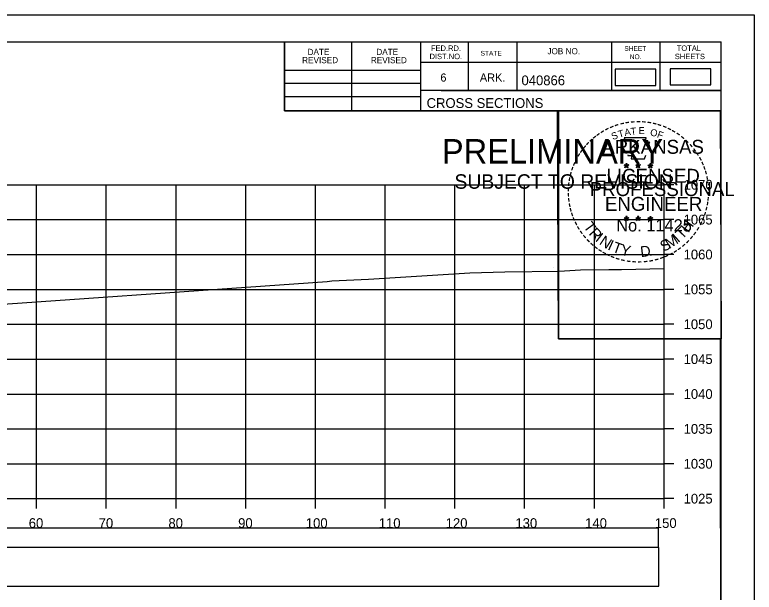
# Model space of a CAD drawing. Extents: x 1370565 to 1374448, y 301010 to 304637.
# Drawn here: x 1370791.9 to 1370898, y 303701.1 to 303783.9 of the extents above; entities that cross this region are included whole.
import ezdxf

# ---------------------------------------------------------------- set-up
doc = ezdxf.new("R2010")
doc.units = 0
for name, color, linetype in [('Default', 7, 'Continuous'), ('R_Axis', 7, 'Continuous'), ('R_Axis Annot', 7, 'Continuous'), ('R_Border', 7, 'Continuous'), ('R_Border PE', 7, 'Continuous'), ('R_Border Prem', 7, 'Continuous'), ('R_Drive', 7, 'Continuous'), ('R_Exist Surface', 7, 'Continuous'), ('R_Grid', 7, 'Continuous'), ('R_No Plot', 7, 'Continuous')]:
    doc.layers.add(name, color=color, linetype=linetype)

msp = doc.modelspace()

# ---------------------------------------------------------------- linework, layer by layer
at = {"layer": 'Default'}
msp.add_lwpolyline([(1370878.02, 303773.77), (1370883.85, 303773.77), (1370883.85, 303776.08), (1370878.02, 303776.08)], close=True, dxfattribs=at)
at = {"layer": 'R_Axis'}
for p, q in [((1370885.03, 303714.53), (1370885.03, 303759.53)), ((1370886.43, 303759.53), (1370885.03, 303759.53)), ((1370886.43, 303754.53), (1370885.03, 303754.53)), ((1370886.43, 303749.53), (1370885.03, 303749.53)), ((1370886.43, 303744.53), (1370885.03, 303744.53)), ((1370886.43, 303739.53), (1370885.03, 303739.53)), ((1370886.43, 303734.53), (1370885.03, 303734.53)), ((1370886.43, 303729.53), (1370885.03, 303729.53)), ((1370886.43, 303724.53), (1370885.03, 303724.53)), ((1370886.43, 303719.53), (1370885.03, 303719.53)), ((1370585.03, 303714.53), (1370885.03, 303714.53)), ((1370795.03, 303713.13), (1370795.03, 303714.53)), ((1370805.03, 303713.13), (1370805.03, 303714.53)), ((1370815.03, 303713.13), (1370815.03, 303714.53)), ((1370825.03, 303713.13), (1370825.03, 303714.53)), ((1370835.03, 303713.13), (1370835.03, 303714.53)), ((1370845.03, 303713.13), (1370845.03, 303714.53)), ((1370855.03, 303713.13), (1370855.03, 303714.53)), ((1370865.03, 303713.13), (1370865.03, 303714.53)), ((1370875.03, 303713.13), (1370875.03, 303714.53)), ((1370885.03, 303713.13), (1370885.03, 303714.53)), ((1370886.43, 303714.53), (1370885.03, 303714.53))]:
    msp.add_line(p, q, dxfattribs=at)
at = {"layer": 'R_Border'}
for p, q in [((1370577.03, 303779.99), (1370893.21, 303779.99)), ((1370830.57, 303770.11), (1370830.57, 303779.99)), ((1370840.25, 303770.11), (1370840.25, 303779.99)), ((1370850.11, 303779.99), (1370850.11, 303770.11)), ((1370856.95, 303779.99), (1370856.95, 303773.05)), ((1370863.89, 303779.99), (1370863.89, 303773.05)), ((1370877.47, 303779.99), (1370877.47, 303773.05)), ((1370884.41, 303779.99), (1370884.41, 303773.05)), ((1370893.21, 303574.53), (1370893.21, 303779.99)), ((1370893.21, 303777.05), (1370850.11, 303777.05)), ((1370893.21, 303777.07), (1370893.21, 303777.07)), ((1370830.57, 303775.97), (1370850.11, 303775.97)), ((1370830.57, 303774.11), (1370850.11, 303774.11)), ((1370893.21, 303773.05), (1370850.11, 303773.05)), ((1370853.07, 303773.05), (1370893.21, 303773.05)), ((1370830.57, 303772.17), (1370850.11, 303772.17)), ((1370893.21, 303770.11), (1370830.57, 303770.11))]:
    msp.add_line(p, q, dxfattribs=at)
at = {"layer": 'R_Border PE'}
for p, q in [((1370879.29, 303762.37), (1370879.64, 303762.26)), ((1370879.29, 303762.37), (1370879.54, 303762.32)), ((1370879.29, 303762.37), (1370879.53, 303762.24)), ((1370879.64, 303762.62), (1370879.6, 303762.37)), ((1370879.64, 303762.26), (1370879.64, 303762.62)), ((1370879.64, 303762.62), (1370879.69, 303762.37)), ((1370879.99, 303762.37), (1370879.64, 303762.26)), ((1370879.99, 303762.37), (1370879.7, 303762.32)), ((1370879.99, 303762.37), (1370879.78, 303762.26)), ((1370880.96, 303762.37), (1370881.31, 303762.26)), ((1370880.96, 303762.37), (1370881.21, 303762.32)), ((1370880.96, 303762.37), (1370881.2, 303762.24)), ((1370881.31, 303762.62), (1370881.27, 303762.37)), ((1370881.31, 303762.26), (1370881.31, 303762.62)), ((1370881.31, 303762.62), (1370881.36, 303762.37)), ((1370881.66, 303762.37), (1370881.31, 303762.26)), ((1370881.66, 303762.37), (1370881.37, 303762.32)), ((1370881.66, 303762.37), (1370881.45, 303762.26)), ((1370882.72, 303762.35), (1370883.07, 303762.24)), ((1370882.72, 303762.35), (1370882.98, 303762.31)), ((1370882.72, 303762.35), (1370882.96, 303762.23)), ((1370883.07, 303762.61), (1370883.03, 303762.36)), ((1370883.07, 303762.24), (1370883.07, 303762.61)), ((1370883.07, 303762.61), (1370883.12, 303762.36)), ((1370883.42, 303762.35), (1370883.07, 303762.24)), ((1370883.42, 303762.35), (1370883.13, 303762.31)), ((1370883.42, 303762.35), (1370883.22, 303762.25)), ((1370879.42, 303761.96), (1370879.64, 303762.26)), ((1370879.42, 303761.96), (1370879.55, 303762.2)), ((1370879.42, 303761.96), (1370879.64, 303762.18)), ((1370879.85, 303761.96), (1370879.64, 303762.26)), ((1370879.85, 303761.96), (1370879.64, 303762.17)), ((1370879.85, 303761.96), (1370879.72, 303762.25)), ((1370881.09, 303761.96), (1370881.31, 303762.26)), ((1370881.09, 303761.96), (1370881.22, 303762.2)), ((1370881.09, 303761.96), (1370881.31, 303762.18)), ((1370881.52, 303761.96), (1370881.31, 303762.26)), ((1370881.52, 303761.96), (1370881.31, 303762.17)), ((1370881.52, 303761.96), (1370881.39, 303762.25)), ((1370882.86, 303761.95), (1370883.07, 303762.24)), ((1370882.86, 303761.95), (1370882.98, 303762.19)), ((1370882.86, 303761.95), (1370883.07, 303762.16)), ((1370883.29, 303761.95), (1370883.07, 303762.24)), ((1370883.29, 303761.95), (1370883.07, 303762.16)), ((1370883.29, 303761.95), (1370883.15, 303762.24)), ((1370879.64, 303755.05), (1370879.59, 303754.8)), ((1370879.64, 303754.68), (1370879.64, 303755.05)), ((1370879.64, 303755.05), (1370879.68, 303754.8)), ((1370881.3, 303755.05), (1370881.26, 303754.8)), ((1370881.3, 303754.68), (1370881.3, 303755.05)), ((1370881.3, 303755.05), (1370881.35, 303754.8)), ((1370883.07, 303755.04), (1370883.03, 303754.79)), ((1370883.07, 303754.67), (1370883.07, 303755.04)), ((1370883.07, 303755.04), (1370883.12, 303754.79)), ((1370879.29, 303754.79), (1370879.64, 303754.68)), ((1370879.29, 303754.79), (1370879.54, 303754.75)), ((1370879.29, 303754.79), (1370879.52, 303754.67)), ((1370879.42, 303754.39), (1370879.64, 303754.68)), ((1370879.42, 303754.39), (1370879.55, 303754.63)), ((1370879.42, 303754.39), (1370879.63, 303754.6)), ((1370879.85, 303754.39), (1370879.63, 303754.6)), ((1370879.98, 303754.79), (1370879.64, 303754.68)), ((1370879.85, 303754.39), (1370879.64, 303754.68)), ((1370879.98, 303754.79), (1370879.7, 303754.74)), ((1370879.85, 303754.39), (1370879.71, 303754.68)), ((1370879.98, 303754.79), (1370879.78, 303754.69)), ((1370880.96, 303754.79), (1370881.3, 303754.68)), ((1370880.96, 303754.79), (1370881.21, 303754.75)), ((1370880.96, 303754.79), (1370881.19, 303754.67)), ((1370881.09, 303754.39), (1370881.3, 303754.68)), ((1370881.09, 303754.39), (1370881.21, 303754.63)), ((1370881.09, 303754.39), (1370881.3, 303754.6)), ((1370881.65, 303754.79), (1370881.3, 303754.68)), ((1370881.52, 303754.39), (1370881.3, 303754.68)), ((1370881.52, 303754.39), (1370881.3, 303754.6)), ((1370881.65, 303754.79), (1370881.37, 303754.74)), ((1370881.52, 303754.39), (1370881.38, 303754.68)), ((1370881.65, 303754.79), (1370881.45, 303754.69)), ((1370882.72, 303754.78), (1370883.07, 303754.67)), ((1370882.72, 303754.78), (1370882.98, 303754.74)), ((1370882.72, 303754.78), (1370882.96, 303754.66)), ((1370882.86, 303754.38), (1370883.07, 303754.67)), ((1370882.86, 303754.38), (1370882.98, 303754.62)), ((1370882.86, 303754.38), (1370883.07, 303754.59)), ((1370883.42, 303754.78), (1370883.07, 303754.67)), ((1370883.28, 303754.38), (1370883.07, 303754.67)), ((1370883.28, 303754.38), (1370883.07, 303754.59)), ((1370883.42, 303754.78), (1370883.13, 303754.73)), ((1370883.28, 303754.38), (1370883.15, 303754.67)), ((1370883.42, 303754.78), (1370883.21, 303754.68))]:
    msp.add_line(p, q, dxfattribs=at)
for points in [[(1370879.33, 303766.24), (1370879.6, 303765.42)], [(1370882.84, 303765.32), (1370882.98, 303765.61), (1370882.3, 303765.58), (1370882.45, 303766.24), (1370879.33, 303766.24)], [(1370879.82, 303763.82), (1370879.82, 303763.73), (1370880.39, 303763.72), (1370880.33, 303763.24), (1370882.2, 303763.24), (1370882.4, 303763.78)], [(1370879.64, 303762.62), (1370879.85, 303761.96), (1370879.29, 303762.37), (1370879.99, 303762.37), (1370879.42, 303761.96), (1370879.64, 303762.62)], [(1370881.31, 303762.62), (1370881.52, 303761.96), (1370880.96, 303762.37), (1370881.66, 303762.37), (1370881.09, 303761.96), (1370881.31, 303762.62)], [(1370883.07, 303762.61), (1370883.29, 303761.95), (1370882.72, 303762.35), (1370883.42, 303762.35), (1370882.86, 303761.95), (1370883.07, 303762.61)], [(1370879.64, 303755.05), (1370879.85, 303754.39), (1370879.29, 303754.79), (1370879.98, 303754.79), (1370879.42, 303754.39), (1370879.64, 303755.05)], [(1370881.3, 303755.05), (1370881.52, 303754.39), (1370880.96, 303754.79), (1370881.65, 303754.79), (1370881.09, 303754.39), (1370881.3, 303755.05)], [(1370883.07, 303755.04), (1370883.28, 303754.38), (1370882.72, 303754.78), (1370883.42, 303754.78), (1370882.86, 303754.38), (1370883.07, 303755.04)]]:
    msp.add_lwpolyline(points, dxfattribs=at)
for centre, radius in [((1370879.64, 303762.26), 0.172), ((1370879.64, 303762.26), 0.145), ((1370879.64, 303762.26), 0.116), ((1370879.64, 303762.26), 0.0991), ((1370879.64, 303762.26), 0.0747), ((1370881.31, 303762.26), 0.172), ((1370881.31, 303762.26), 0.145), ((1370881.31, 303762.26), 0.116), ((1370881.31, 303762.26), 0.0991), ((1370881.31, 303762.26), 0.0747), ((1370883.07, 303762.24), 0.172), ((1370883.07, 303762.24), 0.145), ((1370883.07, 303762.24), 0.116), ((1370883.07, 303762.24), 0.0991), ((1370883.07, 303762.24), 0.0747), ((1370879.64, 303762.26), 0.0495), ((1370879.64, 303762.26), 0.0296), ((1370881.31, 303762.26), 0.0495), ((1370881.31, 303762.26), 0.0296), ((1370883.07, 303762.24), 0.0495), ((1370883.07, 303762.24), 0.0296), ((1370879.63, 303754.68), 0.172), ((1370879.63, 303754.68), 0.145), ((1370879.63, 303754.68), 0.116), ((1370879.63, 303754.68), 0.0991), ((1370879.63, 303754.68), 0.0747), ((1370879.63, 303754.68), 0.0495), ((1370879.63, 303754.68), 0.0296), ((1370881.3, 303754.68), 0.172), ((1370881.3, 303754.68), 0.145), ((1370881.3, 303754.68), 0.116), ((1370881.3, 303754.68), 0.0991), ((1370881.3, 303754.68), 0.0747), ((1370881.3, 303754.68), 0.0495), ((1370881.3, 303754.68), 0.0296), ((1370883.07, 303754.67), 0.172), ((1370883.07, 303754.67), 0.145), ((1370883.07, 303754.67), 0.116), ((1370883.07, 303754.67), 0.0991), ((1370883.07, 303754.67), 0.0747), ((1370883.07, 303754.67), 0.0495), ((1370883.07, 303754.67), 0.0296)]:
    msp.add_circle(centre, radius, dxfattribs=at)
at = {"layer": 'R_Drive'}
for points in [[(1370885.89, 303773.84), (1370891.72, 303773.84), (1370891.72, 303776.15), (1370885.89, 303776.15)], [(1370585.8, 303707.57), (1370884.22, 303707.57), (1370884.22, 303710.28), (1370585.8, 303710.28)], [(1370585.86, 303701.99), (1370884.28, 303701.99), (1370884.28, 303707.52), (1370585.86, 303707.52)]]:
    msp.add_lwpolyline(points, close=True, dxfattribs=at)
at = {"layer": 'R_Exist Surface'}
msp.add_lwpolyline([(1370779.23, 303741.65), (1370836.69, 303745.66), (1370837.37, 303745.75), (1370842.65, 303745.98), (1370857.18, 303746.91), (1370862.19, 303747.02), (1370869.97, 303747.14), (1370873.06, 303747.35), (1370877.11, 303747.4), (1370878.94, 303747.39), (1370885.03, 303747.5)], dxfattribs=at)
at = {"layer": 'R_Grid'}
for p, q in [((1370585.03, 303759.53), (1370885.03, 303759.53)), ((1370795.03, 303714.53), (1370795.03, 303759.53)), ((1370805.03, 303714.53), (1370805.03, 303759.53)), ((1370815.03, 303714.53), (1370815.03, 303759.53)), ((1370825.03, 303714.53), (1370825.03, 303759.53)), ((1370835.03, 303714.53), (1370835.03, 303759.53)), ((1370845.03, 303714.53), (1370845.03, 303759.53)), ((1370855.03, 303714.53), (1370855.03, 303759.53)), ((1370865.03, 303714.53), (1370865.03, 303759.53)), ((1370875.03, 303714.53), (1370875.03, 303759.53)), ((1370885.03, 303714.53), (1370885.03, 303759.53)), ((1370585.03, 303754.53), (1370885.03, 303754.53)), ((1370585.03, 303749.53), (1370885.03, 303749.53)), ((1370585.03, 303744.53), (1370885.03, 303744.53)), ((1370585.03, 303739.53), (1370885.03, 303739.53)), ((1370585.03, 303734.53), (1370885.03, 303734.53)), ((1370585.03, 303729.53), (1370885.03, 303729.53)), ((1370585.03, 303724.53), (1370885.03, 303724.53)), ((1370585.03, 303719.53), (1370885.03, 303719.53)), ((1370585.03, 303714.53), (1370885.03, 303714.53))]:
    msp.add_line(p, q, dxfattribs=at)
at = {"layer": 'R_No Plot'}
for p, q in [((1370564.63, 303783.89), (1370897.96, 303783.89)), ((1370869.24, 303747.66), (1370869.24, 303747.66))]:
    msp.add_line(p, q, dxfattribs=at)
for points in [[(1370564.62, 303783.89), (1370897.96, 303783.89), (1370897.96, 303570.55), (1370564.62, 303570.55)], [(1370810.95, 303779.99), (1370830.57, 303779.99), (1370830.57, 303770.11), (1370846.68, 303770.11), (1370869.88, 303770.11), (1370869.88, 303737.44), (1370893.09, 303737.44), (1370893.21, 303574.53), (1370577.03, 303574.53), (1370577.03, 303779.99)], [(1370869.74, 303770.11), (1370893.09, 303770.11), (1370893.23, 303737.44), (1370869.88, 303737.44)]]:
    msp.add_lwpolyline(points, close=True, dxfattribs=at)

# ---------------------------------------------------------------- texts
at = {"layer": 'R_Axis Annot'}
for s, p in [('1070', (1370887.83, 303758.83)), ('1065', (1370887.83, 303753.83)), ('1060', (1370887.83, 303748.83)), ('1055', (1370887.83, 303743.83)), ('1050', (1370887.83, 303738.83)), ('1045', (1370887.83, 303733.83)), ('1040', (1370887.83, 303728.83)), ('1035', (1370887.83, 303723.83)), ('1030', (1370887.83, 303718.83)), ('1025', (1370887.83, 303713.83)), ('60', (1370793.91, 303710.33)), ('70', (1370803.94, 303710.33)), ('80', (1370813.94, 303710.33)), ('90', (1370823.94, 303710.33)), ('100', (1370833.65, 303710.33)), ('110', (1370844.11, 303710.33)), ('120', (1370853.71, 303710.33)), ('130', (1370863.71, 303710.33)), ('140', (1370873.71, 303710.33)), ('150', (1370883.71, 303710.33))]:
    msp.add_text(s, height=1.4, dxfattribs=at).set_placement(p)
at = {"layer": 'R_Border'}
for s, height, p in [('FED.RD.', 0.782, (1370851.59, 303778.71)), ('SHEET', 0.684, (1370879.33, 303778.71)), ('TOTAL', 0.782, (1370886.85, 303778.71)), ('DATE', 0.879, (1370833.9, 303778.13)), ('DATE', 0.879, (1370843.76, 303778.13)), ('DIST.NO.', 0.782, (1370851.39, 303777.53)), ('STATE', 0.684, (1370858.71, 303778.03)), ('JOB NO.', 0.879, (1370868.29, 303778.23)), ('NO.', 0.684, (1370880.11, 303777.53)), ('SHEETS', 0.782, (1370886.57, 303777.53)), ('REVISED', 0.879, (1370833.12, 303776.95)), ('REVISED', 0.879, (1370842.98, 303776.95)), ('6', 1.17, (1370852.95, 303774.31)), ('ARK.', 1.172, (1370858.61, 303774.31)), ('040866', 1.4, (1370864.58, 303773.79)), ('CROSS SECTIONS', 1.4, (1370850.97, 303770.54))]:
    msp.add_text(s, height=height, rotation=360, dxfattribs=at).set_placement(p)
at = {"layer": 'R_Border PE'}
for s, height, rotation, p in [('-', 1.6, 28.7918, (1370876.81, 303766.79)), ('-', 1.6, 24.3072, (1370877.45, 303767.1)), ('-', 1.6, 19.1761, (1370878.08, 303767.37)), ('-', 1.6, 13.6301, (1370878.83, 303767.61)), ('-', 1.6, 10.2193, (1370879.51, 303767.77)), ('T', 1, 6.0228, (1370880.28, 303766.67)), ('-', 1.6, 5.8968, (1370880.24, 303767.88)), ('-', 1.6, 0.1862, (1370881.01, 303767.96)), ('E', 1, 0.8323, (1370881.38, 303766.78)), ('-', 1.6, 357.743, (1370881.73, 303767.94)), ('-', 1.6, 352.1617, (1370882.48, 303767.89)), ('-', 1.6, 347.2049, (1370883.19, 303767.77)), ('-', 1.6, 342.3362, (1370883.83, 303767.62)), ('-', 1.6, 337.8551, (1370884.56, 303767.4)), ('-', 1.6, 334.1211, (1370885.2, 303767.12)), ('-', 1.6, 38.9507, (1370875.16, 303765.64)), ('-', 1.6, 36.2317, (1370875.64, 303766.02)), ('-', 1.6, 34.0636, (1370876.22, 303766.42)), ('S', 1, 21.594, (1370877.69, 303765.92)), ('T', 1, 16.4036, (1370878.6, 303766.25)), ('A', 1, 11.2132, (1370879.43, 303766.5)), ('O', 1, 350.4515, (1370882.98, 303766.57)), ('F', 1, 340.0707, (1370883.94, 303766.34)), ('-', 1.6, 329.6409, (1370885.77, 303766.84)), ('-', 1.6, 325.8627, (1370886.42, 303766.48)), ('-', 1.6, 48.423, (1370874.28, 303764.75)), ('-', 1.6, 42.9622, (1370874.73, 303765.23)), ('ARKANSAS', 2, 360, (1370876.18, 303763.96)), ('-', 1.6, 320.5297, (1370887.03, 303766.05)), ('-', 1.6, 315.5786, (1370887.63, 303765.57)), ('-', 1.6, 54.2325, (1370873.46, 303763.69)), ('-', 1.6, 50.6142, (1370873.88, 303764.26)), ('-', 1.6, 309.8797, (1370888.2, 303765.02)), ('-', 1.6, 306.6522, (1370888.72, 303764.41)), ('-', 1.6, 62.8713, (1370872.83, 303762.55)), ('-', 1.6, 58.0706, (1370873.14, 303763.17)), ('-', 1.4, 303.6753, (1370889.21, 303763.85)), ('-', 1.6, 299.6684, (1370889.53, 303763.24)), ('-', 1.6, 67.7743, (1370872.57, 303761.94)), ('-', 1.6, 294.6628, (1370889.85, 303762.63)), ('-', 1.6, 75.461, (1370872.15, 303760.6)), ('-', 1.6, 72.3945, (1370872.35, 303761.31)), ('LICENSED', 2, 360, (1370876.78, 303759.81)), ('DWB', 0.01, 360, (1370879.63, 303762.25)), ('DWB', 0.01, 360, (1370881.3, 303762.25)), ('DWB', 0.01, 360, (1370883.06, 303762.24)), ('-', 1.6, 290.5728, (1370890.11, 303762.05)), ('-', 1.6, 285.1233, (1370890.34, 303761.47)), ('-', 1.6, 81.2013, (1370872.02, 303759.89)), ('-', 1.6, 280.5493, (1370890.54, 303760.73)), ('-', 1.6, 85.1863, (1370871.94, 303759.19)), ('PROFESSIONAL', 2, 360, (1370874.36, 303757.9)), ('-', 1.6, 276.5962, (1370890.7, 303759.96)), ('-', 1.6, 274.3301, (1370890.76, 303759.24)), ('-', 1.6, 94.1959, (1370871.95, 303757.77)), ('-', 1.6, 89.0622, (1370871.92, 303758.49)), ('-', 1.6, 269.9407, (1370890.8, 303758.61)), ('-', 1.6, 98.9479, (1370872.03, 303757.1)), ('ENGINEER', 2, 360, (1370876.55, 303755.78)), ('-', 1.6, 260.9953, (1370890.71, 303757.29)), ('-', 1.6, 263.5172, (1370890.78, 303757.94)), ('-', 1.6, 101.7149, (1370872.16, 303756.37)), ('-', 1.6, 105.4578, (1370872.32, 303755.77)), ('-', 1.6, 255.7626, (1370890.6, 303756.61)), ('-', 1.6, 109.0874, (1370872.54, 303755.14)), ('-', 1.6, 114.0643, (1370872.79, 303754.55)), ('-', 1.6, 247.8887, (1370890.19, 303755.22)), ('-', 1.6, 252.8681, (1370890.42, 303755.89)), ('-', 1.6, 115.7289, (1370873.1, 303753.93)), ('T', 1.54, 306.0406, (1370873.4, 303753.52)), ('No. 11425', 1.757, 360, (1370878.17, 303752.83)), ('DWB', 0.01, 360, (1370879.62, 303754.68)), ('DWB', 0.01, 360, (1370881.29, 303754.68)), ('DWB', 0.01, 360, (1370883.06, 303754.67)), ('H', 1.54, 54.6088, (1370888.52, 303752.56)), ('-', 1.6, 244.6197, (1370889.93, 303754.59)), ('-', 1.6, 120.4471, (1370873.45, 303753.34)), ('-', 1.6, 125.8934, (1370873.86, 303752.78)), ('R', 1.54, 314.005, (1370874.16, 303752.47)), ('T', 1.54, 46.6444, (1370887.63, 303751.61)), ('-', 1.6, 233.8452, (1370889.13, 303753.18)), ('-', 1.6, 239.0712, (1370889.54, 303753.83)), ('-', 1.6, 130.7181, (1370874.32, 303752.23)), ('-', 1.6, 134.2238, (1370874.84, 303751.68)), ('I', 1.54, 321.9694, (1370875.06, 303751.54)), ('N', 1.54, 326.5002, (1370875.63, 303751.07)), ('S', 1.54, 26.9312, (1370884.94, 303749.88)), ('M', 1.54, 32.6563, (1370885.78, 303750.29)), ('I', 1.54, 42.1136, (1370887.06, 303751.14)), ('-', 1.6, 231.2538, (1370888.7, 303752.62)), ('-', 1.6, 138.9338, (1370875.36, 303751.22)), ('-', 1.6, 144.6463, (1370875.92, 303750.81)), ('I', 1.54, 335.3603, (1370876.83, 303750.28)), ('T', 1.54, 339.8912, (1370877.49, 303749.96)), ('Y', 1.54, 347.8556, (1370878.71, 303749.51)), ('D', 1.54, 6.3969, (1370881.7, 303749.15)), ('-', 1.6, 221.0851, (1370887.7, 303751.54)), ('-', 1.6, 225.7653, (1370888.23, 303752.05)), ('-', 1.6, 148.0898, (1370876.48, 303750.44)), ('-', 1.6, 151.5704, (1370877.06, 303750.12)), ('-', 1.6, 154.6002, (1370877.58, 303749.87)), ('.', 1.54, 13.7642, (1370882.89, 303749.28)), ('-', 1.6, 207.3568, (1370886.06, 303750.34)), ('-', 1.6, 212.2491, (1370886.62, 303750.68)), ('-', 1.6, 215.7363, (1370887.15, 303751.07)), ('-', 1.6, 158.5612, (1370878.2, 303749.62)), ('-', 1.6, 162.7983, (1370878.89, 303749.4)), ('-', 1.6, 167.5555, (1370879.6, 303749.24)), ('-', 1.6, 173.1155, (1370880.38, 303749.13)), ('-', 1.6, 176.5183, (1370881.12, 303749.08)), ('-', 1.6, 181.5918, (1370881.87, 303749.1)), ('-', 1.6, 185.8167, (1370882.68, 303749.17)), ('-', 1.6, 191.2858, (1370883.41, 303749.3)), ('-', 1.6, 195.4743, (1370884.14, 303749.5)), ('-', 1.6, 200.7184, (1370884.82, 303749.75)), ('-', 1.6, 204.2516, (1370885.44, 303750.02))]:
    msp.add_text(s, height=height, rotation=rotation, dxfattribs=at).set_placement(p)
at = {"layer": 'R_Border Prem'}
for s, height, p in [('PRELIMINARY', 3.5, (1370853.16, 303762.57)), ('DWB', 0.01, (1370853.9, 303764.42)), ('SUBJECT TO REVISION', 2.0751, (1370854.97, 303758.95))]:
    msp.add_text(s, height=height, rotation=360, dxfattribs=at).set_placement(p)

doc.saveas('drawing.dxf')
